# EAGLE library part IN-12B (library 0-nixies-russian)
IN-12B: medium numeric topview nixie tube
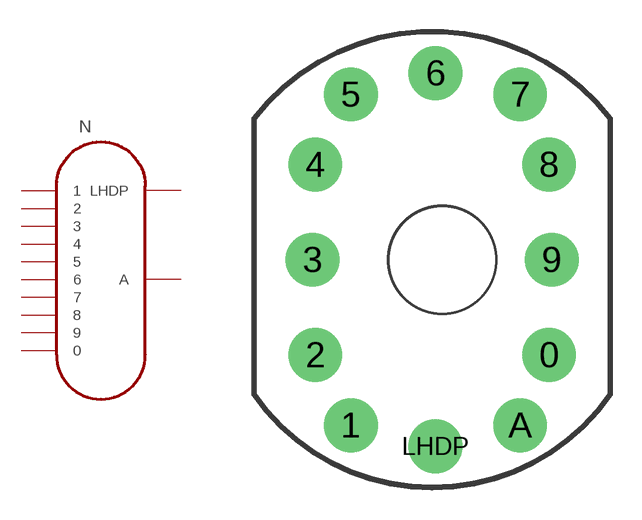
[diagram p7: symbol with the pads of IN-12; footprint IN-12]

Designator prefix N

## IN-12B  [IN-12]
0  0
1  1
2  2
3  3
4  4
5  5
6  6
7  7
8  8
9  9
A  A
LHDP  LHDP

## Footprint IN-12 (pad centres in mm)
May be used with socket: SK-136
drill 1.1 pad 2.54 round: 0 5.048,-4.5; 1 -4.317,-7.817; 2 -6,-4.5; 3 -6.127,0; 4 -6,4.5; 5 -4.317,7.817; 6 -0.318,8.818; 7 3.683,7.817; 8 5.048,4.5; 9 5.175,0; A 3.683,-7.817; LHDP -0.318,-8.818
hole 5 at 0,0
